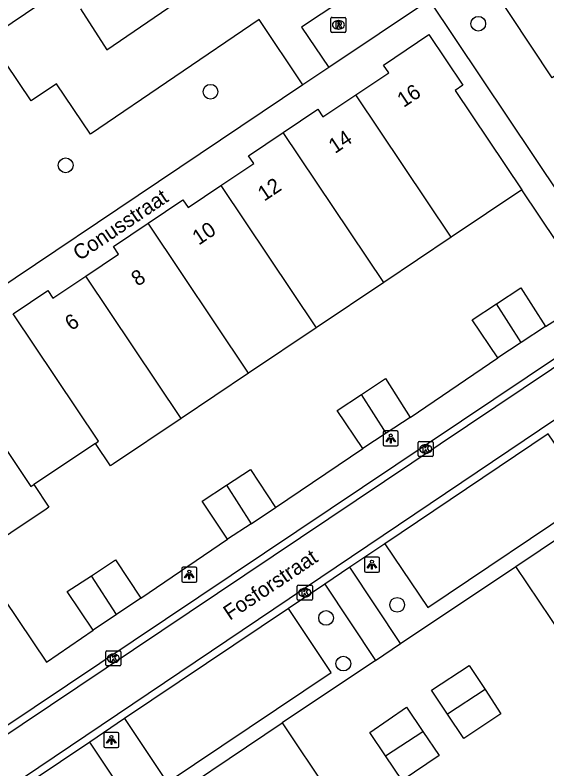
# Model space of a CAD drawing. Extents: x 158797 to 159887, y 384318 to 385255.
# Drawn here: x 159135 to 159170.3, y 384529.2 to 384579.2 of the extents above; entities that cross this region are included whole.
import ezdxf

# ---------------------------------------------------------------- set-up
doc = ezdxf.new("R2010")
doc.units = 0
for name, color, linetype in [('IMGEO_Boom', 7, 'Continuous'), ('IMGEO_Groenvoorziening', 7, 'Continuous'), ('IMGEO_Kolk', 7, 'Continuous'), ('IMGEO_Lichtpunt', 7, 'Continuous'), ('IMGEO_Openbare_ruimte_label', 7, 'Continuous'), ('IMGEO_Pand', 7, 'Continuous'), ('IMGEO_Pand_nummerreeks', 7, 'Continuous'), ('IMGEO_Parkeervlak_open', 7, 'Continuous'), ('IMGEO_Rijbaan_lokaal_open', 7, 'Continuous'), ('IMGEO_Rioolput', 7, 'Continuous'), ('IMGEO_Voetpad_gesloten', 7, 'Continuous'), ('IMGEO_Voetpad_open', 7, 'Continuous')]:
    doc.layers.add(name, color=color, linetype=linetype)

msp = doc.modelspace()

# ---------------------------------------------------------------- linework, layer by layer
at = {"layer": 'IMGEO_Boom'}
for centre in [(159165.773, 384578.672), (159148.008, 384574.158), (159138.394, 384569.278), (159160.395, 384540.119), (159155.676, 384539.248), (159156.821, 384536.222)]:
    msp.add_circle(centre, 0.489, dxfattribs=at)
at = {"layer": 'IMGEO_Groenvoorziening'}
for points in [[(159160.626, 384537.545), (159168.272, 384542.666)], [(159158.952, 384536.424), (159152.769, 384532.283)]]:
    msp.add_lwpolyline(points, dxfattribs=at)
at = {"layer": 'IMGEO_Kolk'}
for p, q in [((159161.792, 384550.032), (159161.792, 384550.884)), ((159161.867, 384550.958), (159162.719, 384550.958)), ((159162.28, 384550.738), (159162.305, 384550.738)), ((159162.793, 384550.884), (159162.793, 384550.032)), ((159162.303, 384550.178), (159162.278, 384550.178)), ((159162.719, 384549.958), (159161.867, 384549.958)), ((159153.766, 384540.499), (159153.766, 384541.351)), ((159153.841, 384541.425), (159154.693, 384541.425)), ((159154.254, 384541.205), (159154.279, 384541.205)), ((159154.767, 384541.351), (159154.767, 384540.499)), ((159154.277, 384540.645), (159154.252, 384540.645)), ((159154.693, 384540.425), (159153.841, 384540.425)), ((159141.055, 384536.139), (159141.055, 384536.991)), ((159141.13, 384537.065), (159141.982, 384537.065)), ((159142.056, 384536.991), (159142.056, 384536.139)), ((159141.543, 384536.845), (159141.568, 384536.845)), ((159141.982, 384536.065), (159141.13, 384536.065)), ((159141.566, 384536.285), (159141.541, 384536.285))]:
    msp.add_line(p, q, dxfattribs=at)
for points in [[(159161.792, 384550.032), (159161.792, 384550.884)], [(159161.867, 384550.958), (159162.719, 384550.958)], [(159162.113, 384550.658), (159162.236, 384550.658), (159162.236, 384550.507), (159162.366, 384550.658), (159162.53, 384550.658), (159162.384, 384550.507), (159162.537, 384550.258), (159162.385, 384550.258), (159162.3, 384550.422), (159162.236, 384550.355), (159162.236, 384550.258), (159162.113, 384550.258), (159162.113, 384550.658)], [(159162.793, 384550.884), (159162.793, 384550.032)], [(159162.719, 384549.958), (159161.867, 384549.958)], [(159153.766, 384540.499), (159153.766, 384541.351)], [(159153.841, 384541.425), (159154.693, 384541.425)], [(159154.087, 384541.125), (159154.21, 384541.125), (159154.21, 384540.974), (159154.34, 384541.125), (159154.504, 384541.125), (159154.358, 384540.974), (159154.511, 384540.725), (159154.359, 384540.725), (159154.274, 384540.889), (159154.21, 384540.822), (159154.21, 384540.725), (159154.087, 384540.725), (159154.087, 384541.125)], [(159154.767, 384541.351), (159154.767, 384540.499)], [(159154.693, 384540.425), (159153.841, 384540.425)], [(159141.055, 384536.139), (159141.055, 384536.991)], [(159141.13, 384537.065), (159141.982, 384537.065)], [(159142.056, 384536.991), (159142.056, 384536.139)], [(159141.376, 384536.765), (159141.499, 384536.765), (159141.499, 384536.614), (159141.629, 384536.765), (159141.793, 384536.765), (159141.647, 384536.614), (159141.8, 384536.365), (159141.648, 384536.365), (159141.563, 384536.529), (159141.499, 384536.462), (159141.499, 384536.365), (159141.376, 384536.365), (159141.376, 384536.765)], [(159141.982, 384536.065), (159141.13, 384536.065)]]:
    msp.add_lwpolyline(points, dxfattribs=at)
for centre, start, end in [((159161.869, 384550.882), 91.552, 178.448), ((159161.869, 384550.882), 91.552, 178.448), ((159162.717, 384550.882), 1.552, 88.448), ((159162.717, 384550.882), 1.552, 88.448), ((159161.869, 384550.034), 181.552, 268.448), ((159161.869, 384550.034), 181.552, 268.448), ((159162.717, 384550.034), 271.552, 358.448), ((159162.717, 384550.034), 271.552, 358.448), ((159153.843, 384541.349), 91.552, 178.448), ((159153.843, 384541.349), 91.552, 178.448), ((159154.691, 384541.349), 1.552, 88.448), ((159154.691, 384541.349), 1.552, 88.448), ((159153.843, 384540.501), 181.552, 268.448), ((159153.843, 384540.501), 181.552, 268.448), ((159154.691, 384540.501), 271.552, 358.448), ((159154.691, 384540.501), 271.552, 358.448), ((159141.132, 384536.989), 91.552, 178.448), ((159141.132, 384536.989), 91.552, 178.448), ((159141.98, 384536.989), 1.552, 88.448), ((159141.98, 384536.989), 1.552, 88.448), ((159141.132, 384536.141), 181.552, 268.448), ((159141.132, 384536.141), 181.552, 268.448), ((159141.98, 384536.141), 271.552, 358.448), ((159141.98, 384536.141), 271.552, 358.448)]:
    msp.add_arc(centre, 0.0765, start, end, dxfattribs=at)
for centre, major_axis, ratio, start_param, end_param in [((159162.279, 384550.458), (-0.387, 0.002), 0.722429, 4.712389, 7.853982), ((159162.304, 384550.458), (-0.39, 0.002), 0.717154, 1.570796, 4.712389), ((159154.253, 384540.925), (-0.387, 0.002), 0.722429, 4.712389, 7.853982), ((159154.278, 384540.925), (-0.39, 0.002), 0.717154, 1.570796, 4.712389), ((159141.542, 384536.565), (-0.387, 0.002), 0.722429, 4.712389, 7.853982), ((159141.567, 384536.565), (-0.39, 0.002), 0.717154, 1.570796, 4.712389)]:
    msp.add_ellipse(centre, major_axis=major_axis, ratio=ratio, start_param=start_param, end_param=end_param, dxfattribs=at)
at = {"layer": 'IMGEO_Lichtpunt'}
for p, q in [((159159.468, 384551.56), (159159.468, 384550.753)), ((159159.468, 384551.56), (159159.468, 384550.753)), ((159160.37, 384551.655), (159159.562, 384551.655)), ((159160.37, 384551.655), (159159.562, 384551.655)), ((159160.464, 384550.753), (159160.464, 384551.56)), ((159160.464, 384550.753), (159160.464, 384551.56)), ((159159.562, 384550.659), (159160.37, 384550.659)), ((159159.562, 384550.659), (159160.37, 384550.659)), ((159158.222, 384543.186), (159158.222, 384542.379)), ((159158.222, 384543.186), (159158.222, 384542.379)), ((159159.124, 384543.281), (159158.316, 384543.281)), ((159159.124, 384543.281), (159158.316, 384543.281)), ((159159.218, 384542.379), (159159.218, 384543.186)), ((159159.218, 384542.379), (159159.218, 384543.186)), ((159146.101, 384542.527), (159146.101, 384541.72)), ((159146.101, 384542.527), (159146.101, 384541.72)), ((159147.003, 384542.622), (159146.195, 384542.622)), ((159147.003, 384542.622), (159146.195, 384542.622)), ((159147.097, 384541.72), (159147.097, 384542.527)), ((159147.097, 384541.72), (159147.097, 384542.527)), ((159158.316, 384542.285), (159159.124, 384542.285)), ((159158.316, 384542.285), (159159.124, 384542.285)), ((159146.195, 384541.626), (159147.003, 384541.626)), ((159146.195, 384541.626), (159147.003, 384541.626)), ((159140.929, 384531.557), (159140.929, 384530.75)), ((159140.929, 384531.557), (159140.929, 384530.75)), ((159141.831, 384531.652), (159141.023, 384531.652)), ((159141.831, 384531.652), (159141.023, 384531.652)), ((159141.925, 384530.75), (159141.925, 384531.557)), ((159141.925, 384530.75), (159141.925, 384531.557)), ((159141.023, 384530.656), (159141.831, 384530.656)), ((159141.023, 384530.656), (159141.831, 384530.656))]:
    msp.add_line(p, q, dxfattribs=at)
for points in [[(159159.842, 384551.224), (159159.881, 384551.196), (159159.693, 384550.934), (159159.655, 384550.961), (159159.842, 384551.224)], [(159159.944, 384551.176), (159159.991, 384551.176), (159159.991, 384550.854), (159159.944, 384550.854), (159159.944, 384551.176)], [(159160.054, 384551.196), (159160.092, 384551.223), (159160.279, 384550.961), (159160.24, 384550.933), (159160.054, 384551.196)], [(159158.596, 384542.85), (159158.635, 384542.822), (159158.447, 384542.56), (159158.409, 384542.587), (159158.596, 384542.85)], [(159158.698, 384542.802), (159158.745, 384542.802), (159158.745, 384542.48), (159158.698, 384542.48), (159158.698, 384542.802)], [(159158.808, 384542.822), (159158.846, 384542.849), (159159.033, 384542.587), (159158.994, 384542.559), (159158.808, 384542.822)], [(159146.475, 384542.191), (159146.514, 384542.163), (159146.326, 384541.901), (159146.288, 384541.928), (159146.475, 384542.191)], [(159146.577, 384542.143), (159146.624, 384542.143), (159146.624, 384541.821), (159146.577, 384541.821), (159146.577, 384542.143)], [(159146.687, 384542.163), (159146.725, 384542.19), (159146.912, 384541.928), (159146.873, 384541.9), (159146.687, 384542.163)], [(159141.303, 384531.221), (159141.342, 384531.193), (159141.154, 384530.931), (159141.116, 384530.958), (159141.303, 384531.221)], [(159141.405, 384531.173), (159141.452, 384531.173), (159141.452, 384530.851), (159141.405, 384530.851), (159141.405, 384531.173)], [(159141.515, 384531.193), (159141.553, 384531.22), (159141.74, 384530.958), (159141.701, 384530.93), (159141.515, 384531.193)]]:
    msp.add_lwpolyline(points, dxfattribs=at)
for centre in [(159159.967, 384551.358), (159158.721, 384542.984), (159146.6, 384542.325), (159141.428, 384531.355)]:
    msp.add_circle(centre, 0.0994, dxfattribs=at)
for centre, start, end in [((159159.562, 384551.56), 90, 180), ((159159.562, 384551.56), 90, 180), ((159160.37, 384551.56), 0, 90), ((159160.37, 384551.56), 0, 90), ((159159.562, 384550.753), 180, 270), ((159159.562, 384550.753), 180, 270), ((159160.37, 384550.753), 270, 0), ((159160.37, 384550.753), 270, 360), ((159158.316, 384543.186), 90, 180), ((159158.316, 384543.186), 90, 180), ((159159.124, 384543.186), 0, 90), ((159159.124, 384543.186), 0, 90), ((159146.195, 384542.527), 90, 180), ((159146.195, 384542.527), 90, 180), ((159147.003, 384542.527), 0, 90), ((159147.003, 384542.527), 0, 90), ((159158.316, 384542.379), 180, 270), ((159158.316, 384542.379), 180, 270), ((159159.124, 384542.379), 270, 0), ((159159.124, 384542.379), 270, 360), ((159146.195, 384541.72), 180, 270), ((159146.195, 384541.72), 180, 270), ((159147.003, 384541.72), 270, 0), ((159147.003, 384541.72), 270, 360), ((159141.023, 384531.557), 90, 180), ((159141.023, 384531.557), 90, 180), ((159141.831, 384531.557), 0, 90), ((159141.831, 384531.557), 0, 90), ((159141.023, 384530.75), 180, 270), ((159141.023, 384530.75), 180, 270), ((159141.831, 384530.75), 270, 0), ((159141.831, 384530.75), 270, 360)]:
    msp.add_arc(centre, 0.0946, start, end, dxfattribs=at)
at = {"layer": 'IMGEO_Pand'}
for points in [[(159157.652, 384573.962), (159159.832, 384575.423), (159159.493, 384575.93), (159162.502, 384577.947), (159164.751, 384574.591), (159164.244, 384574.251), (159168.665, 384567.656)], [(159152.833, 384571.457), (159155.132, 384573.006), (159155.472, 384572.5), (159157.652, 384573.962)], [(159163.984, 384564.515), (159157.652, 384573.962)], [(159148.695, 384567.94), (159150.876, 384569.403), (159150.535, 384569.909), (159152.833, 384571.457)], [(159159.501, 384561.508), (159152.833, 384571.457)], [(159143.873, 384565.435), (159146.174, 384566.984), (159146.515, 384566.478), (159148.695, 384567.94)], [(159148.695, 384567.94), (159155.021, 384558.502)], [(159168.665, 384567.656), (159163.984, 384564.515)], [(159139.731, 384561.919), (159141.913, 384563.379), (159141.572, 384563.885), (159143.873, 384565.435)], [(159150.536, 384555.493), (159143.873, 384565.435)], [(159163.984, 384564.515), (159159.501, 384561.508)], [(159134.907, 384559.415), (159137.208, 384560.965), (159137.548, 384560.459), (159139.731, 384561.919)], [(159146.053, 384552.486), (159139.731, 384561.919)], [(159159.501, 384561.508), (159155.021, 384558.502)], [(159166.98, 384560.091), (159168.59, 384561.144), (159170.24, 384558.583)], [(159167.069, 384556.505), (159165.369, 384559.037), (159166.98, 384560.091)], [(159168.63, 384557.528), (159166.98, 384560.091)], [(159140.37, 384550.832), (159140.57, 384550.966), (159134.907, 384559.415)], [(159155.021, 384558.502), (159150.536, 384555.493)], [(159170.24, 384558.583), (159168.63, 384557.528)], [(159168.63, 384557.528), (159167.069, 384556.505)], [(159130.769, 384555.904), (159136.089, 384547.966), (159136.282, 384548.095)], [(159150.536, 384555.493), (159146.053, 384552.486)], [(159158.024, 384554.069), (159159.628, 384555.128), (159161.266, 384552.545)], [(159158.113, 384550.49), (159156.419, 384553.009), (159158.024, 384554.069)], [(159159.674, 384551.508), (159158.024, 384554.069)], [(159161.266, 384552.545), (159159.674, 384551.508)], [(159146.053, 384552.486), (159141.568, 384549.477), (159141.371, 384549.345), (159140.37, 384550.832)], [(159159.674, 384551.508), (159158.113, 384550.49)], [(159140.37, 384550.832), (159136.282, 384548.095)], [(159149.066, 384548.048), (159150.667, 384549.093), (159152.311, 384546.572)], [(159136.282, 384548.095), (159137.289, 384546.591), (159137.097, 384546.463), (159132.401, 384543.329)], [(159149.146, 384544.465), (159147.465, 384547.003), (159149.066, 384548.048)], [(159149.066, 384548.048), (159150.706, 384545.503)], [(159168.272, 384542.666), (159176.212, 384547.991)], [(159150.706, 384545.503), (159152.311, 384546.572)], [(159150.706, 384545.503), (159149.146, 384544.465)], [(159140.11, 384542.044), (159141.713, 384543.096), (159143.38, 384540.559)], [(159171.356, 384538.068), (159168.272, 384542.666)], [(159140.211, 384538.431), (159138.506, 384540.992), (159140.11, 384542.044)], [(159141.765, 384539.475), (159140.11, 384542.044)], [(159143.38, 384540.559), (159141.765, 384539.475)], [(159141.765, 384539.475), (159140.211, 384538.431)], [(159163.74, 384532.866), (159162.674, 384534.463), (159165.171, 384536.104), (159166.226, 384534.5)], [(159166.226, 384534.5), (159167.28, 384532.896), (159164.812, 384531.259), (159163.74, 384532.866)], [(159166.226, 384534.5), (159163.74, 384532.866)], [(159159.622, 384530.098), (159158.577, 384531.648), (159161.008, 384533.33), (159162.093, 384531.723)], [(159143.371, 384525.955), (159152.769, 384532.283)], [(159152.769, 384532.283), (159155.843, 384527.695)], [(159162.093, 384531.723), (159163.178, 384530.115), (159160.722, 384528.467), (159159.622, 384530.098)], [(159159.622, 384530.098), (159162.093, 384531.723)]]:
    msp.add_lwpolyline(points, dxfattribs=at)
at = {"layer": 'IMGEO_Parkeervlak_open'}
for points in [[(159159.576, 384544.176), (159162.426, 384539.948), (159173.284, 384547.242), (159170.423, 384551.464)], [(159142.311, 384532.584), (159145.136, 384528.341), (159156.017, 384535.628), (159153.19, 384539.87)]]:
    msp.add_lwpolyline(points, dxfattribs=at)
at = {"layer": 'IMGEO_Rijbaan_lokaal_open'}
for points in [[(159195.001, 384572.021), (159178.017, 384560.678), (159131.797, 384529.704), (159111.782, 384559.411)], [(159130.515, 384532.465), (159131.92, 384530.403), (159177.742, 384561.091), (159194.721, 384572.428)], [(159190.205, 384527.153), (159192.762, 384528.848), (159193.039, 384528.419), (159151.428, 384500.515), (159133.468, 384527.238), (159175.064, 384555.242), (159175.35, 384554.823), (159172.804, 384553.09)], [(159170.423, 384551.464), (159159.576, 384544.176)], [(159159.576, 384544.176), (159157.252, 384542.609)], [(159157.252, 384542.609), (159155.589, 384541.488)], [(159155.589, 384541.488), (159153.19, 384539.87)], [(159153.19, 384539.87), (159142.311, 384532.584)], [(159142.311, 384532.584), (159140.006, 384531.001)], [(159140.006, 384531.001), (159134.158, 384527.09), (159136.335, 384523.829)]]:
    msp.add_lwpolyline(points, dxfattribs=at)
at = {"layer": 'IMGEO_Rioolput'}
for p, q in [((159155.996, 384578.17), (159155.996, 384579.022)), ((159156.071, 384579.096), (159156.923, 384579.096)), ((159156.997, 384579.022), (159156.997, 384578.17)), ((159156.484, 384578.876), (159156.509, 384578.876)), ((159156.923, 384578.096), (159156.071, 384578.096)), ((159156.507, 384578.316), (159156.482, 384578.316))]:
    msp.add_line(p, q, dxfattribs=at)
for points in [[(159155.996, 384578.17), (159155.996, 384579.022)], [(159156.071, 384579.096), (159156.923, 384579.096)], [(159156.997, 384579.022), (159156.997, 384578.17)], [(159156.585, 384578.794), (159156.333, 384578.796), (159156.333, 384578.396)], [(159156.333, 384578.396), (159156.457, 384578.396), (159156.457, 384578.558), (159156.468, 384578.558)], [(159156.511, 384578.715), (159156.457, 384578.715), (159156.457, 384578.634)], [(159156.457, 384578.634), (159156.509, 384578.634)], [(159156.515, 384578.529), (159156.586, 384578.396), (159156.726, 384578.396), (159156.661, 384578.522)], [(159156.923, 384578.096), (159156.071, 384578.096)]]:
    msp.add_lwpolyline(points, dxfattribs=at)
for centre, radius, start, end in [((159156.073, 384579.02), 0.0765, 91.552, 178.448), ((159156.073, 384579.02), 0.0765, 91.552, 178.448), ((159156.921, 384579.02), 0.0765, 1.552, 88.448), ((159156.921, 384579.02), 0.0765, 1.552, 88.448), ((159156.467, 384578.505), 0.0533, 26.0293, 88.6989), ((159156.493, 384578.823), 0.19, 274.7715, 282.9687), ((159156.517, 384578.619), 0.0964, 77.0061, 93.1865), ((159156.531, 384578.676), 0.0378, 276.6634, 79.6772), ((159156.584, 384578.684), 0.109, 350.3612, 89.416), ((159156.582, 384578.684), 0.112, 277.5842, 350.9817), ((159156.566, 384578.469), 0.108, 29.5134, 73.7905), ((159156.073, 384578.172), 0.0765, 181.552, 268.448), ((159156.073, 384578.172), 0.0765, 181.552, 268.448), ((159156.921, 384578.172), 0.0765, 271.552, 358.448), ((159156.921, 384578.172), 0.0765, 271.552, 358.448)]:
    msp.add_arc(centre, radius, start, end, dxfattribs=at)
for centre, major_axis, ratio, start_param, end_param in [((159156.483, 384578.596), (-0.387, 0.002), 0.722429, 4.712389, 7.853982), ((159156.508, 384578.596), (-0.39, 0.002), 0.717154, 1.570796, 4.712389)]:
    msp.add_ellipse(centre, major_axis=major_axis, ratio=ratio, start_param=start_param, end_param=end_param, dxfattribs=at)
at = {"layer": 'IMGEO_Voetpad_gesloten'}
for points in [[(159139.375, 384579.667), (159141.123, 384576.932), (159150.625, 384583.433), (159151.747, 384581.759), (159165.041, 384590.724), (159170.605, 384582.437), (159174.689, 384585.159), (159179.297, 384578.512), (159193.347, 384588.107), (159197.808, 384581.483), (159198.988, 384582.307), (159199.249, 384581.925), (159200.917, 384582.98), (159201.158, 384582.618), (159202.847, 384583.73)], [(159193.8, 384573.756), (159197.584, 384576.354), (159193.706, 384582.105), (159191.156, 384580.471), (159190.067, 384582.131), (159177.557, 384573.685), (159174.848, 384577.908), (159170.678, 384575.093), (159165.114, 384583.512), (159164.29, 384582.941), (159163.188, 384584.508), (159154.051, 384578.453), (159155.852, 384575.778)], [(159121.518, 384572.043), (159122.57, 384570.491), (159138.377, 384581.17)], [(159154.128, 384574.62), (159151.236, 384578.957), (159140.054, 384571.334), (159137.783, 384574.681), (159136.096, 384573.552), (159134.423, 384576.062), (159117.809, 384564.747), (159117.376, 384564.452)], [(159155.852, 384575.778), (159154.128, 384574.62)]]:
    msp.add_lwpolyline(points, dxfattribs=at)
at = {"layer": 'IMGEO_Voetpad_open'}
for points in [[(159171.232, 384567.261), (159162.529, 384580.264), (159155.852, 384575.778)], [(159154.128, 384574.62), (159124.093, 384554.441), (159117.376, 384564.452)], [(159170.24, 384558.583), (159173.398, 384560.595), (159168.665, 384567.656)], [(159161.266, 384552.545), (159167.069, 384556.505)], [(159152.311, 384546.572), (159158.113, 384550.49)], [(159143.38, 384540.559), (159149.146, 384544.465)], [(159132.401, 384543.329), (159137.124, 384536.304), (159140.211, 384538.431)], [(159160.626, 384537.545), (159157.252, 384542.609)], [(159155.589, 384541.488), (159158.952, 384536.424)], [(159158.952, 384536.424), (159160.626, 384537.545)], [(159143.371, 384525.955), (159140.006, 384531.001)]]:
    msp.add_lwpolyline(points, dxfattribs=at)

# ---------------------------------------------------------------- texts
at = {"layer": 'IMGEO_Openbare_ruimte_label'}
for s, rotation, p in [('Conusstraat', 33.9125, (159139.313, 384562.914)), ('Fosforstraat', 33.8649, (159149.287, 384539.058))]:
    msp.add_text(s, height=1, rotation=rotation, dxfattribs=at).set_placement(p)
at = {"layer": 'IMGEO_Pand_nummerreeks'}
for s, rotation, p in [('16', 33.844, (159160.822, 384573.077)), ('14', 33.844, (159156.266, 384570.022)), ('12', 33.8479, (159151.57, 384566.858)), ('10', 33.8479, (159147.226, 384563.945)), ('8', 33.79, (159143.172, 384561.214)), ('6', 33.7873, (159138.77, 384558.268))]:
    msp.add_text(s, height=1, rotation=rotation, dxfattribs=at).set_placement(p)

doc.saveas('drawing.dxf')
